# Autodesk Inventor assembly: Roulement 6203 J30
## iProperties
Author: Administrateur
Created: 2004-01
Part Number: Roulement 6203 J30
Catalog Web Link: www.traceparts.com
Description: Roulements à une rangée de billes à contact radial ouvert - pour arbre Ø17
Vendor: SNR
Document SubType Name: Assemblage
Standard: 6203 J30
Designer: Administrateur
Control State: 0
Master: False
Checked Out: False
PropertySet Name: Design Tracking Control
Shininess: 41.0
Angle Display Precision: 2
Document Length Units: 11269
Document Angle Units: 11283
Document Time Units: 11279
Document Mass Units: 11290
Document Length Units Precision: 3
Document Angle Units Precision: 2
Compacted: False
PropertySet Name: _Private Model Information
Density: 0.0
Volumn: 0.0
Area: 0.0
PropertySet Name: Model Information
